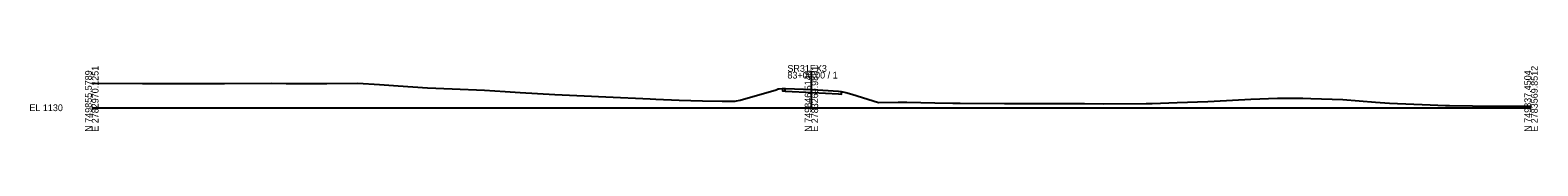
# Model space of a CAD drawing. Extents: x 1199974 to 1204603, y 1199988 to 1202535.
# Drawn here: x 1203974 to 1204603, y 1201990 to 1202018 of the extents above; entities that cross this region are included whole.
import ezdxf

# ---------------------------------------------------------------- set-up
doc = ezdxf.new("R2010")
doc.units = 0
for name, color, linetype in [('Section', 7, 'Continuous'), ('SURVEY - DTM GRAPHICS - Triangles', 7, 'Continuous'), ('SURVEY - TRANSPORTATION - Features', 7, 'Continuous'), ('XSCell', 7, 'Continuous')]:
    doc.layers.add(name, color=color, linetype=linetype)

msp = doc.modelspace()

# ---------------------------------------------------------------- linework, layer by layer
at = {"layer": 'SURVEY - DTM GRAPHICS - Triangles'}
for points in [[(1204000, 1202010.3), (1204001.42, 1202010.28), (1204021.09, 1202010.14), (1204027.73, 1202010.08), (1204030.51, 1202010.09), (1204034.96, 1202010.12), (1204046.56, 1202010.11), (1204053.62, 1202010.1), (1204055.31, 1202010.08), (1204075.09, 1202010.28), (1204081.05, 1202010.16), (1204094.24, 1202010.1), (1204098.04, 1202010.12), (1204110.88, 1202010.19), (1204119.98, 1202009.67), (1204127.69, 1202009.13), (1204139.93, 1202008.26), (1204150.28, 1202007.86), (1204163.71, 1202007.32), (1204172.4, 1202006.74), (1204178.54, 1202006.39), (1204193, 1202005.54), (1204205.21, 1202004.98), (1204214.28, 1202004.5), (1204232.75, 1202003.7), (1204235.18, 1202003.59), (1204244.83, 1202003.24), (1204254.66, 1202002.91), (1204262.75, 1202002.81), (1204268.2, 1202002.78), (1204268.8, 1202002.96), (1204270.36, 1202003.15), (1204285.33, 1202007.54), (1204286.19, 1202007.84), (1204286.56, 1202007.88), (1204287.93, 1202008)], [(1204312.48, 1202006.7), (1204313.07, 1202006.61), (1204314.4, 1202006.42), (1204316.85, 1202005.62), (1204327.98, 1202002.24), (1204336.18, 1202002.38), (1204339.73, 1202002.4), (1204351.47, 1202002.07), (1204358.96, 1202001.88), (1204362.07, 1202001.89), (1204380.53, 1202001.83), (1204388.17, 1202001.8), (1204391.17, 1202001.81), (1204402.71, 1202001.78), (1204413.8, 1202001.8), (1204421.76, 1202001.67), (1204439.49, 1202001.78), (1204442.09, 1202001.81), (1204452.44, 1202002.17), (1204465.3, 1202002.67), (1204467.93, 1202002.82), (1204483.23, 1202003.57), (1204494.26, 1202003.94), (1204494.84, 1202003.96), (1204504.89, 1202004.03), (1204508.21, 1202003.86), (1204521.48, 1202003.46), (1204535.14, 1202002.38), (1204541.03, 1202001.87), (1204557.92, 1202001.21), (1204564.36, 1202000.95), (1204566, 1202000.91), (1204585.2, 1202000.71), (1204592.04, 1202000.68), (1204600, 1202000.65)]]:
    msp.add_lwpolyline(points, dxfattribs=at)
at = {"layer": 'SURVEY - TRANSPORTATION - Features'}
for points in [[(1204287.93, 1202008), (1204287.93, 1202007), (1204287.93, 1202007), (1204289.17, 1202006.95), (1204300.5, 1202006.42), (1204311.27, 1202005.77), (1204311.27, 1202005.77), (1204312.48, 1202005.7), (1204312.48, 1202005.7), (1204312.48, 1202006.7), (1204312.48, 1202006.7), (1204311.27, 1202006.77), (1204311.27, 1202006.77), (1204300.5, 1202007.42), (1204289.17, 1202007.95), (1204287.93, 1202008), (1204287.93, 1202008)], [(1204287.93, 1202008), (1204287.93, 1202007), (1204289.05, 1202006.95), (1204289.05, 1202007.95), (1204287.93, 1202008)]]:
    msp.add_lwpolyline(points, dxfattribs=at)
at = {"layer": 'XSCell'}
for p, q in [((1204300, 1202000), (1204300, 1202015)), ((1204000, 1202000), (1204300, 1202000)), ((1204300, 1202000), (1204600, 1202000))]:
    msp.add_line(p, q, dxfattribs=at)

# ---------------------------------------------------------------- texts
at = {"layer": 'Section'}
msp.add_text('-', height=0.0001, dxfattribs=at).set_placement((1204000, 1202000))
at = {"layer": 'XSCell'}
for s, p in [('N 749855.5789', (1204000, 1201990)), ('E 2782970.1251', (1204002.8, 1201990)), ('N 749846.5146', (1204300, 1201990)), ('E 2783269.9881', (1204302.8, 1201990)), ('N 749837.4504', (1204600, 1201990)), ('E 2783569.8512', (1204602.8, 1201990))]:
    msp.add_text(s, height=2.8, rotation=90, dxfattribs=at).set_placement(p)
for s, p in [('83+00.00 / 1', (1204290, 1202012.2)), ('SR31EX3', (1204290, 1202015)), ('EL 1130', (1203974, 1201998.6))]:
    msp.add_text(s, height=2.8, dxfattribs=at).set_placement(p)

doc.saveas('drawing.dxf')
